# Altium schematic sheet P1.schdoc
size 297 x 209 mm; Symbol: Drawing-Symbol_A4; @Project Name: Macropad; @Page Count: 1; @Update Date: 2026-11-06; @Create Date: 2026-11-06; @Schematic Name: Schematic1; @Page No: 1; @Page Name: P1; Company: EasyEDA.com; Version: V1.0; Page Size: A4; Device: Drawing-Symbol_A4; @Create Time: 21:02:07; @Update Time: 21:02:07; Border: 1; Width: 1170; Height: 825; Region Start: 1; X Region Count: 6; Y Region Count: 4; Blade Width: 10; Title Block Position: 3; @Board Name: Board1
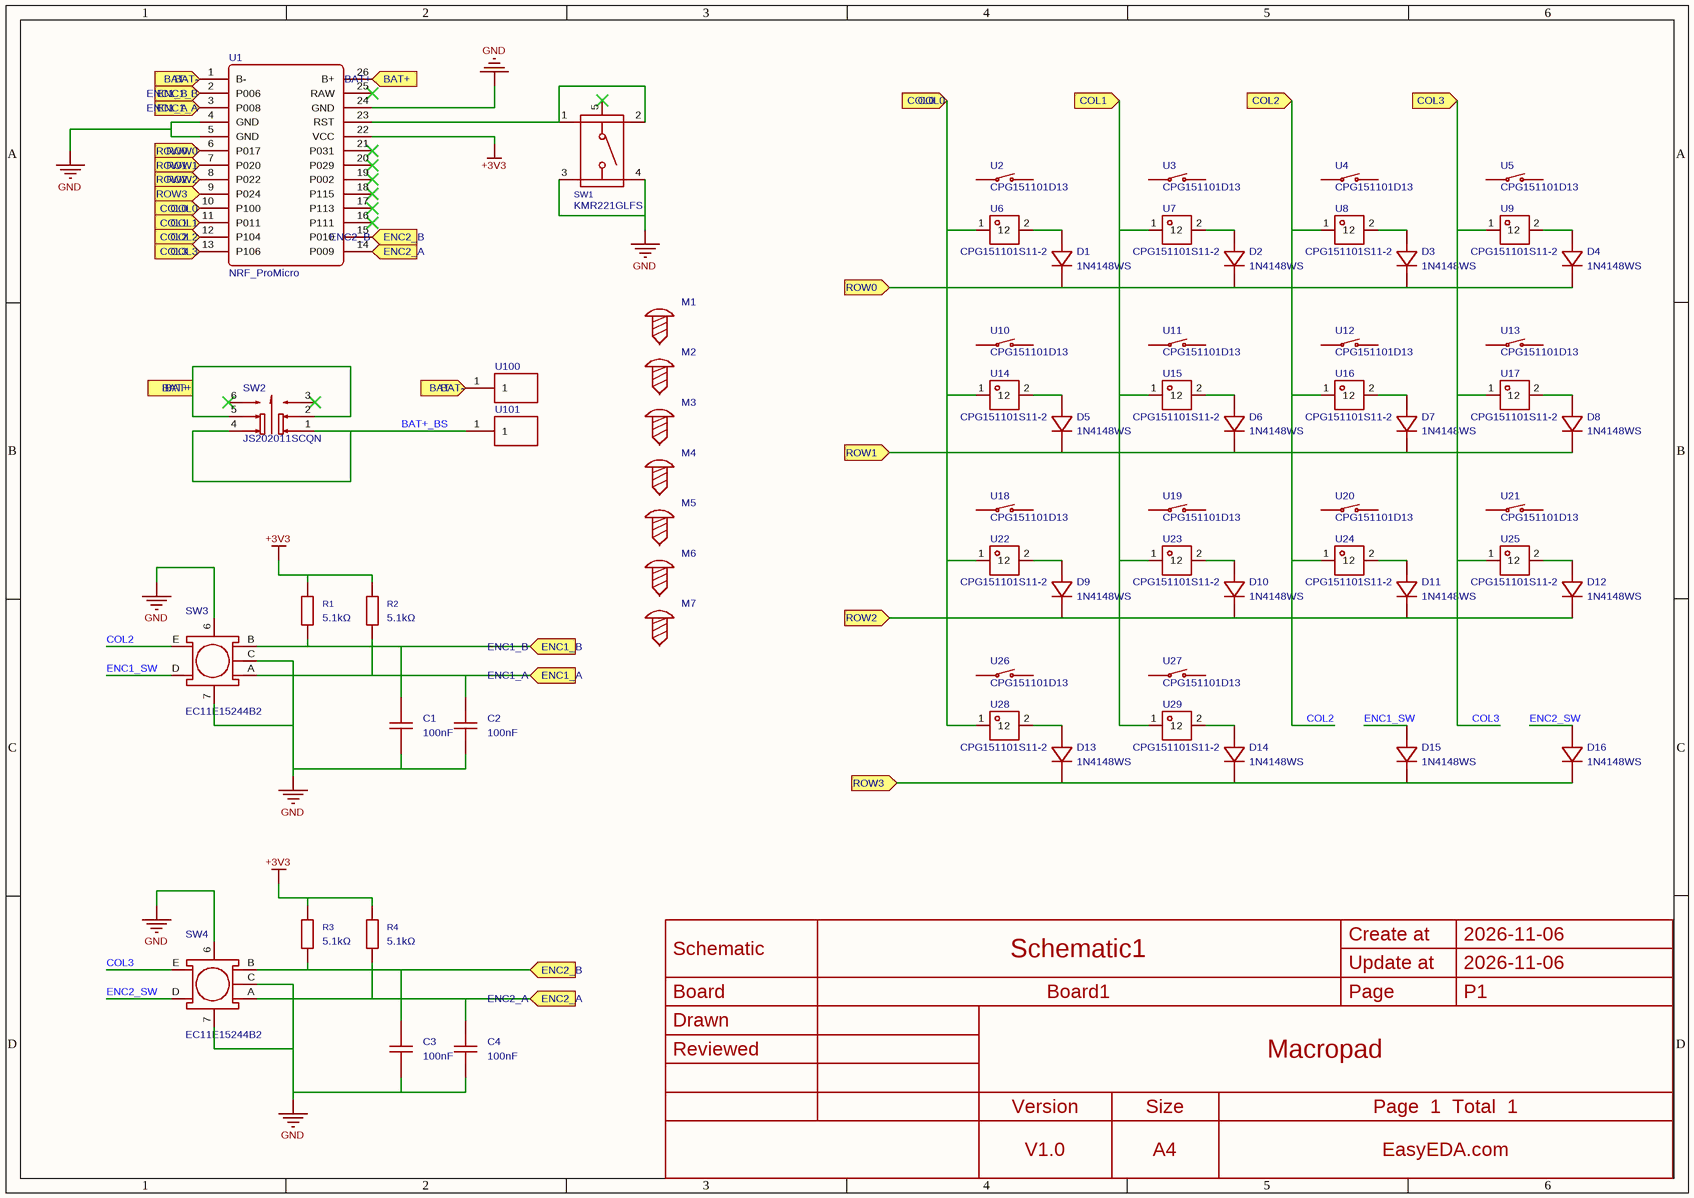
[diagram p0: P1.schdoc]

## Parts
C1  100nF  [C0402]
C2  100nF  [C0402]
C3  100nF  [C0402]
C4  100nF  [C0402]
D1  1N4148WS  [SOD-323_L1.8-W1.3-LS2.5-RD]
D2  1N4148WS  [SOD-323_L1.8-W1.3-LS2.5-RD]
D3  1N4148WS  [SOD-323_L1.8-W1.3-LS2.5-RD]
D4  1N4148WS  [SOD-323_L1.8-W1.3-LS2.5-RD]
D5  1N4148WS  [SOD-323_L1.8-W1.3-LS2.5-RD]
D6  1N4148WS  [SOD-323_L1.8-W1.3-LS2.5-RD]
D7  1N4148WS  [SOD-323_L1.8-W1.3-LS2.5-RD]
D8  1N4148WS  [SOD-323_L1.8-W1.3-LS2.5-RD]
D9  1N4148WS  [SOD-323_L1.8-W1.3-LS2.5-RD]
D10  1N4148WS  [SOD-323_L1.8-W1.3-LS2.5-RD]
D11  1N4148WS  [SOD-323_L1.8-W1.3-LS2.5-RD]
D12  1N4148WS  [SOD-323_L1.8-W1.3-LS2.5-RD]
D13  1N4148WS  [SOD-323_L1.8-W1.3-LS2.5-RD]
D14  1N4148WS  [SOD-323_L1.8-W1.3-LS2.5-RD]
D15  1N4148WS  [SOD-323_L1.8-W1.3-LS2.5-RD]
D16  1N4148WS  [SOD-323_L1.8-W1.3-LS2.5-RD]
M1  (no value)  [Screw-Hole-M2]
M2  (no value)  [Screw-Hole-M2]
M3  (no value)  [Screw-Hole-M2]
M4  (no value)  [Screw-Hole-M2]
M5  (no value)  [Screw-Hole-M3]
M6  (no value)  [Screw-Hole-M3]
M7  (no value)  [Screw-Hole-M3]
R1  5.1kΩ  [R0402]
R2  5.1kΩ  [R0402]
R3  5.1kΩ  [R0402]
R4  5.1kΩ  [R0402]
SW1  KMR221GLFS  [KEY-SMD_KMR2XXGXXX]
SW2  JS202011SCQN  [SW-SMD_JS202011SCQN]
SW3  EC11E15244B2  [SW-TH_EC11XXXXXXXX]
SW4  EC11E15244B2  [SW-TH_EC11XXXXXXXX]
U1  NRF_ProMicro  [NRF_Pro_Micro]
U2  CPG151101D13  [KEY-TH_CPG151101D21X]
U3  CPG151101D13  [KEY-TH_CPG151101D21X]
U4  CPG151101D13  [KEY-TH_CPG151101D21X]
U5  CPG151101D13  [KEY-TH_CPG151101D21X]
U6  CPG151101S11-2  [TH_L10.9-W5.9-CPG151101S11-2]
U7  CPG151101S11-2  [TH_L10.9-W5.9-CPG151101S11-2]
U8  CPG151101S11-2  [TH_L10.9-W5.9-CPG151101S11-2]
U9  CPG151101S11-2  [TH_L10.9-W5.9-CPG151101S11-2]
U10  CPG151101D13  [KEY-TH_CPG151101D21X]
U11  CPG151101D13  [KEY-TH_CPG151101D21X]
U12  CPG151101D13  [KEY-TH_CPG151101D21X]
U13  CPG151101D13  [KEY-TH_CPG151101D21X]
U14  CPG151101S11-2  [TH_L10.9-W5.9-CPG151101S11-2]
U15  CPG151101S11-2  [TH_L10.9-W5.9-CPG151101S11-2]
U16  CPG151101S11-2  [TH_L10.9-W5.9-CPG151101S11-2]
U17  CPG151101S11-2  [TH_L10.9-W5.9-CPG151101S11-2]
U18  CPG151101D13  [KEY-TH_CPG151101D21X]
U19  CPG151101D13  [KEY-TH_CPG151101D21X]
U20  CPG151101D13  [KEY-TH_CPG151101D21X]
U21  CPG151101D13  [KEY-TH_CPG151101D21X]
U22  CPG151101S11-2  [TH_L10.9-W5.9-CPG151101S11-2]
U23  CPG151101S11-2  [TH_L10.9-W5.9-CPG151101S11-2]
U24  CPG151101S11-2  [TH_L10.9-W5.9-CPG151101S11-2]
U25  CPG151101S11-2  [TH_L10.9-W5.9-CPG151101S11-2]
U26  CPG151101D13  [KEY-TH_CPG151101D21X]
U27  CPG151101D13  [KEY-TH_CPG151101D21X]
U28  CPG151101S11-2  [TH_L10.9-W5.9-CPG151101S11-2]
U29  CPG151101S11-2  [TH_L10.9-W5.9-CPG151101S11-2]
U100  (no value)  [Pad2mmx4mm]
U101  (no value)  [Pad2mmx4mm]

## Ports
BAT+ (in), BAT- (in), COL0 (in), COL1 (in), COL2 (in), COL3 (in), ENC1_A (in), ENC1_B (in), ENC2_A (in), ENC2_B (in), ROW0 (in), ROW1 (in), ROW2 (in), ROW3 (in)

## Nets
+3V3: R1.1 R2.1 R3.1 R4.1 U1.22(VCC)
GND: C1.1 C2.1 C3.1 C4.1 SW1.3 SW1.4 SW3.6 SW3.7 SW3.C SW4.6 SW4.7 SW4.C U1.4(GND) U1.5(GND) U1.24(GND)
BAT+: SW2.2 SW2.5 U1.26(B+) ; port BAT+
BAT+_BS: SW2.1 SW2.4 U101.1
BAT-: U1.1(B-) U100.1 ; port BAT-
COL0: U1.10(P100) U6.1 U14.1 U22.1 U28.1 ; port COL0
COL1: U1.11(P011) U7.1 U15.1 U23.1 U29.1 ; port COL1
COL2: SW3.E U1.12(P104) U8.1 U16.1 U24.1 ; port COL2
COL3: SW4.E U1.13(P106) U9.1 U17.1 U25.1 ; port COL3
ENC1_A: C2.2 R2.2 SW3.A U1.3(P008) ; port ENC1_A
ENC1_B: C1.2 R1.2 SW3.B U1.2(P006) ; port ENC1_B
ENC1_SW: D15.2(A) SW3.D
ENC2_A: C4.2 R4.2 SW4.A U1.14(P009) ; port ENC2_A
ENC2_B: C3.2 R3.2 SW4.B U1.15(P010) ; port ENC2_B
ENC2_SW: D16.2(A) SW4.D
ROW0: D1.1(C) D2.1(C) D3.1(C) D4.1(C) U1.6(P017) ; port ROW0
ROW1: D5.1(C) D6.1(C) D7.1(C) D8.1(C) U1.7(P020) ; port ROW1
ROW2: D9.1(C) D10.1(C) D11.1(C) D12.1(C) U1.8(P022) ; port ROW2
ROW3: D13.1(C) D14.1(C) D15.1(C) D16.1(C) U1.9(P024) ; port ROW3
NetD1_2: D1.2(A) U6.2
NetD2_2: D2.2(A) U7.2
NetD3_2: D3.2(A) U8.2
NetD4_2: D4.2(A) U9.2
NetD5_2: D5.2(A) U14.2
NetD6_2: D6.2(A) U15.2
NetD7_2: D7.2(A) U16.2
NetD8_2: D8.2(A) U17.2
NetD9_2: D9.2(A) U22.2
NetD10_2: D10.2(A) U23.2
NetD11_2: D11.2(A) U24.2
NetD12_2: D12.2(A) U25.2
NetD13_2: D13.2(A) U28.2
NetD14_2: D14.2(A) U29.2
NetSW1_1: SW1.1 SW1.2 U1.23(RST)

Not connected (* = marked no-connect by the designer): M1 1; M2 1; M3 1; M4 1; M5 1; M6 1; M7 1; SW1 5*; SW2 3* 6*; U1 16(P111)* 17(P113)* 18(P115)* 19(P002)* 20(P029)* 21(P031)* 25(RAW)*

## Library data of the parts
C1-C4 = CL05B104KB54PNC: Capacitance:100nF Tolerance:±10% Tolerance:±10% Voltage Rating:50V Temperature Coefficient:X7R; Manufacturer: SAMSUNG(三星); AddInBom: yes; ModelId: b7d13df3e9464d7a99d0651d1a5b4d570819f05c4eef4c71ace90d822a990e87; ModelName: C0402_L1.0-W0.5-H0.5; ModelTransform: 39.37,19.685,0,0,0,0,0,0,0; Tolerance: ±10%; Voltage Rating: 50V; Temperature Coefficient: X7R
D1 = 1N4148WS_C917117: Diode Configuration:Standalone Pd - Power Dissipation:200mW Current - Rectified:200mA Voltage - DC Reverse(Vr):75V Voltage - Forward(Vf@If):1.25V@150mA Non-Repetitive Peak Forward Surge Current:2A Reverse Leakage Current (Ir):1uA@75V Reverse Recovery Time; Manufacturer: JSMSEMI(杰盛微); AddInBom: yes; ModelId: 533ebfb2f206414f9035ed0ccba1097d0819f05c4eef4c71ace90d822a990e87; ModelTransform: 104.3305,51.181,0,0,0,0,0,-0.004,0; Pd - Power Dissipation: 200mW; Current - Rectified: 200mA; Voltage - DC Reverse(Vr): 75V; Non-Repetitive Peak Forward Surge Current: 2A; Reverse Recovery Time (trr): 4ns; Operating Junction Temperature Range: -55℃~+150℃
D2-D16 = 1N4148WS_C917117: Diode Configuration:Standalone Pd - Power Dissipation:200mW Current - Rectified:200mA Voltage - DC Reverse(Vr):75V Voltage - Forward(Vf@If):1.25V@150mA Non-Repetitive Peak Forward Surge Current:2A Reverse Leakage Current (Ir):1uA@75V Reverse Recovery Time; Manufacturer: JSMSEMI(杰盛微); 3D Model: 533ebfb2f206414f9035ed0ccba1097d0819f05c4eef4c71ace90d822a990e87; 3D Model Transform: 104.3305,51.181,0,0,0,0,0,-0.004,0; Pd - Power Dissipation: 200mW; Current - Rectified: 200mA; Voltage - DC Reverse(Vr): 75V; Non-Repetitive Peak Forward Surge Current: 2A; Reverse Recovery Time (trr): 4ns; Operating Junction Temperature Range: -55℃~+150℃; AddInBom: yes
M1-M4 = Screw-Hole-M2: AddInBom: yes
M5-M7 = Screw-Hole-M3: ConvertToPcb: yes
R1-R4 = 0402WGF5101TCE: Type:Thick Film Resistor Resistance:5.1kΩ Tolerance:±1% Tolerance:±1% Power(Watts):62.5mW Voltage-Supply(Max):50V Temperature Coefficient:±100ppm/℃ Temperature Coefficient:±100ppm/℃ Operating Temperature:-55℃~+155℃ Operating Temperature:-55℃~+155℃; Manufacturer: UNI-ROYAL(厚声); 3D Model: efdecb7dae4442949d28eecaf748420f0819f05c4eef4c71ace90d822a990e87; 3D Model Transform: 39.37,19.685,0,0,0,0,0,0,0; Tolerance: ±1%; Power(Watts): 62.5mW; Voltage-Supply(Max): 50V; AddInBom: yes; ModelName: R0402_L1.0-W0.5-H0.4
SW1 = KMR221GLFS: Circuit:SPST Actuator Style:Round Button Operating Force:200gf Mounting Style:Brick nogging Switch Length:4.6mm Switch Width:2.8mm Switch Height:1.9mm Contact Current:50mA Voltage Rating (DC):32V With Lamp:- Pin Style:Gull Wing Mechanical Life:- Operating; Manufacturer: C&K; AddInBom: yes; ModelId: 3a2b494b21af49a89e49f1b8920640b50819f05c4eef4c71ace90d822a990e87; ModelName: KEY-SMD_5P-L4.2-W2.8-H1.9-LS4.6-P1.6; ModelTransform: 181.102,111.91088,0,0,0,0,0,-13.071,0; Circuit: SPST; Operating Force: 200gf; Switch Length: 4.6mm; Switch Width: 2.8mm; Switch Height: 1.9mm; Contact Current: 50mA; Voltage Rating (DC): 32V
SW2 = JS202011SCQN: Circuit:DPDT Actuator Style:Rectangular columnar Pin Style:SMDSplicing Switch Height:5.5mm Mounting Style:Brick nogging Current Rating (DC):300mA Voltage Rating (DC):6V Current Rating (AC):- Voltage Rating (AC):- Mechanical Life:5千次 Operating Temperature:; Manufacturer: C&K; AddInBom: yes; ModelId: 026ac03a3b7c4cf9831127f5db2c954a0819f05c4eef4c71ace90d822a990e87; ModelTransform: 354.52134,295.275,0,0,0,0,0,0,0; Circuit: DPDT; Switch Height: 5.5mm; Current Rating (DC): 300mA; Voltage Rating (DC): 6V; Mechanical Life: 5千次
SW3 SW4 = EC11E15244B2_C470754: Encoder Type:Incremental Number of Detents / Pulses (Incremental):30/15 Output Form:Two-phase output Mounting Type:Straight Current Rating (Max):10mA Rated Voltage (Max):5V Operating Temperature:-40℃~+85℃ Operating Temperature:-40℃~+85℃; Manufacturer: ALPSALPINE(阿尔卑斯阿尔派); 3D Model: 34d0052b40b94bce9e3816cf478199620819f05c4eef4c71ace90d822a990e87; 3D Model Transform: 495.18696,578.739,0,0,0,0,0,0,-137.795; Number of Detents / Pulses (Incremental): 30/15; Current Rating (Max): 10mA; Rated Voltage (Max): 5V; AddInBom: yes; ModelName: SW-TH_EC11XXXXXXXX-L11.7-W12.0-H24.5-P2.5-LS14.5
U1 = NRF_ProMicro: AddInBom: yes
U2 = CPG151101D13: Axis Type:Blue Switch Operation Force:50gf Conduction Travel:2.2mm Voltage Rating:12V Operating Temperature:-40℃~+70℃ Operating Temperature:-40℃~+70℃; Manufacturer: HanElectricity(瀚源); AddInBom: yes; ModelId: 22105fb3b67d4e778b6cbc994b8f7b7e0819f05c4eef4c71ace90d822a990e87; ModelName: KEY-TH_L15.6-W14.0-H15.3; ModelTransform: 614.172,551.18,0,90,0,0,25,-150,-137.795; Operation Force: 50gf; Conduction Travel: 2.2mm; Voltage Rating: 12V
U3-U5 U10-U13 U18-U21 U26 U27 = CPG151101D13: Axis Type:Blue Switch Operation Force:50gf Conduction Travel:2.2mm Voltage Rating:12V Operating Temperature:-40℃~+70℃ Operating Temperature:-40℃~+70℃; Manufacturer: HanElectricity(瀚源); 3D Model: 22105fb3b67d4e778b6cbc994b8f7b7e0819f05c4eef4c71ace90d822a990e87; 3D Model Transform: 614.172,551.18,0,90,0,0,25,-150,-137.795; Operation Force: 50gf; Conduction Travel: 2.2mm; Voltage Rating: 12V; AddInBom: yes; ModelName: KEY-TH_L15.6-W14.0-H15.3
U6 = CPG151101S11-2_C49352235: Number of Pins:2 Life:5,000 cycles Operation Force:3000gf Voltage Rating:12V; Manufacturer: HanElectricity(瀚源); AddInBom: yes; ModelId: 2bfeb1828cfe4bcebb28acd50a1b75280819f05c4eef4c71ace90d822a990e87; ModelName: TH_L10.9-W5.9-CPG151101S11; ModelTransform: 570.865,231.8893,0,0,0,0,0,0,-47.244; Operation Force: 3000gf; Voltage Rating: 12V
U7-U9 U14-U17 U22-U25 U28 U29 = CPG151101S11-2_C49352235: Number of Pins:2 Life:5,000 cycles Operation Force:3000gf Voltage Rating:12V; Manufacturer: HanElectricity(瀚源); 3D Model: 2bfeb1828cfe4bcebb28acd50a1b75280819f05c4eef4c71ace90d822a990e87; 3D Model Transform: 570.865,231.8893,0,0,0,0,0,0,-47.244; Operation Force: 3000gf; Voltage Rating: 12V; AddInBom: yes; ModelName: TH_L10.9-W5.9-CPG151101S11
U100 U101 = Pad 2mmx4mm: AddInBom: yes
